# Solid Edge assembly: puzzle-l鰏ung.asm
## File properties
Author: Susi
Template: Normal.asm
Last saved by: Susi
Revision: 3
Application: Solid Edge
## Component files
Holzrahmen.par
Teil1.par
Teil6.par
Teil2.par
Teil3.par
teil8.par
Teil4.par
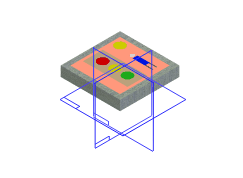
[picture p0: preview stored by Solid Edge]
